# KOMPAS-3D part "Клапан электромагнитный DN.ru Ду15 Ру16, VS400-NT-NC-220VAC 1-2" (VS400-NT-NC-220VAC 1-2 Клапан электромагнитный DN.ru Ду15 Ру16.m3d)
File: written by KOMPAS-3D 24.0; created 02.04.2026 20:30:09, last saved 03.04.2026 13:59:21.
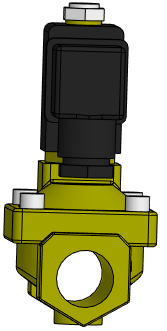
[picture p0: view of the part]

Document properties: Автор: artio; Полное имя файла: C:\Users\artio\OneDrive\Рабочий стол\Клапан электромагнитный DN.ru VS4x-xT-NC-x\VS400-NT-NC\VS400-NT-NC-220VAC 1-2 Клапан электромагнитный DN.ru Ду15 Ру16.m3d

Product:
- Body: Тело 1  | qty 1
    Масса: 1.030062
- Part/product: Клапан электромагнитный DN.ru Ду15 Ру16  | designation VS400-NT-NC-220VAC 1-2
    Масса: 0.759
    Раздел спецификации: Прочие изделия
    Примечание: D130-04661
    additional columns: ef56311e-7521-43dc-8291-0e6108b3d81d; VS400-ET-NC-220VAC 1-2; artio; c; Шероховатость не задана; Да

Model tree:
1. Операция без истории:1

Expressions: VS400-NT-NC-220VAC 1-2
